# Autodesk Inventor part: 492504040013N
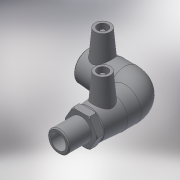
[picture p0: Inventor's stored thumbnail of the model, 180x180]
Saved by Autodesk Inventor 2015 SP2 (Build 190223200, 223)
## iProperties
Created: 2017-06
Part Number: 492504040013N
Material: Generic
Description: PLASSON 90° ELBOW MALE TRANSITION 40 x 11⁄4"
Document SubType Name: Modeling
Designer: KIM
Mass: 225.34 g
Surface Area: 566.959 cm^2
Volume: 225.34 cm^3
Density: 1 g/cm^3
Appearance: Default
Author: KIM
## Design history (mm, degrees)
derived "492504.ipt"
feature "Solid1::492504.ipt"
tag "TaggingFeature1"
body "Solid1"
other parameters: "d2" = 56, "d4" = 31.33333, "d5" = 50.4, "d8" = 168 deg, "d10" = 17.6, "d11" = 5.86667, "d29" = 47, "d30" = 15, "d31" = 51.7, "d34" = 5 deg, "d41" = 4, "d42" = 14, "d43" = 0, "d48" = 66, "d50" = 34, "d51" = 17.6, "d52" = 44, "d54" = 90 deg, "d58" = 44, "d59" = 0, "d61" = 90 deg, "d86" = 3, "d87" = 0, "d93" = 0.1, "d94" = 14.75, "d95" = 41.91, "d96" = 29.337, "d98" = 59, "d99" = 56, "d100" = 53.1, "d102" = 2, "d106" = 0, "L_" = 153, "L_1" = 44, "A_" = 47, "d_2" = 12, "L_2" = 59, "D_1" = 56, "R_" = 41.91
